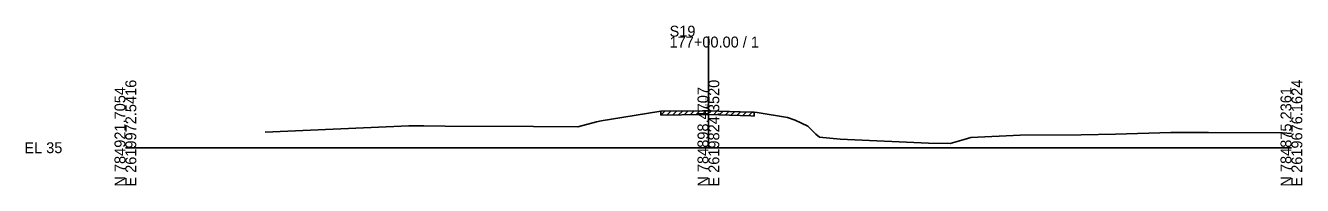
# Model space of a CAD drawing. Extents: x -26 to 1603, y -10 to 5028.
# Drawn here: x -25.7 to 302.8, y 1990.3 to 2031.4 of the extents above; entities that cross this region are included whole.
import ezdxf

# ---------------------------------------------------------------- set-up
doc = ezdxf.new("R2010")
doc.units = 0
for name, color, linetype in [('RD_GPK_XS_Cell', 7, 'Continuous'), ('RD_XS_ExGround', 7, 'Continuous'), ('RD_XS_ExPaveRet', 7, 'Continuous'), ('RD_XS_TX_Elev_EX', 7, 'Continuous')]:
    doc.layers.add(name, color=color, linetype=linetype)

msp = doc.modelspace()

# ---------------------------------------------------------------- linework, layer by layer
at = {"layer": 'RD_GPK_XS_Cell'}
for p, q in [((150, 2000), (150, 2028.57)), ((0, 2000), (150, 2000)), ((150, 2000), (300, 2000))]:
    msp.add_line(p, q, dxfattribs=at)
at = {"layer": 'RD_XS_ExGround'}
for p, q in [((122.45, 2006.93), (127.75, 2007.8)), ((127.75, 2007.8), (137.8, 2009.38)), ((137.8, 2009.38), (148.48, 2009.51)), ((148.48, 2009.51), (149.94, 2009.52)), ((149.94, 2009.52), (160.93, 2009.18)), ((160.93, 2009.18), (161.78, 2009.15)), ((161.78, 2009.15), (162.53, 2009.02)), ((162.53, 2009.02), (170.38, 2007.76)), ((170.38, 2007.76), (172.3, 2007.09)), ((35.98, 2003.99), (72.9, 2005.65)), ((72.9, 2005.65), (76.81, 2005.62)), ((76.81, 2005.62), (82.27, 2005.51)), ((82.27, 2005.51), (105.02, 2005.48)), ((105.02, 2005.48), (116.41, 2005.4)), ((116.41, 2005.4), (121.17, 2006.64)), ((121.17, 2006.64), (122.45, 2006.93)), ((172.3, 2007.09), (175.55, 2005.52)), ((175.55, 2005.52), (177.64, 2003.46)), ((177.64, 2003.46), (178.57, 2002.71)), ((178.57, 2002.71), (183.87, 2002.19)), ((183.87, 2002.19), (206.64, 2001.18)), ((206.64, 2001.18), (212.18, 2001.11)), ((212.18, 2001.11), (215.78, 2002.16)), ((215.78, 2002.16), (217.5, 2002.61)), ((217.5, 2002.61), (230.2, 2003.21)), ((230.2, 2003.21), (245.89, 2003.31)), ((245.89, 2003.31), (254.71, 2003.52)), ((254.71, 2003.52), (268.94, 2003.9)), ((268.94, 2003.9), (278.69, 2003.93)), ((278.69, 2003.93), (297.7, 2003.85)), ((297.7, 2003.85), (300, 2003.62))]:
    msp.add_line(p, q, dxfattribs=at)
at = {"layer": 'RD_XS_ExPaveRet'}
for p, q in [((137.8, 2008.38), (138.81, 2009.39)), ((137.8, 2008.38), (137.8, 2009.38)), ((137.8, 2008.38), (148.48, 2008.51)), ((139.3, 2008.39), (140.31, 2009.41)), ((140.8, 2008.41), (141.81, 2009.43)), ((142.3, 2008.43), (143.31, 2009.44)), ((143.8, 2008.45), (144.81, 2009.46)), ((145.3, 2008.47), (146.31, 2009.48)), ((146.8, 2008.49), (147.81, 2009.5)), ((148.3, 2008.5), (149.31, 2009.52)), ((148.48, 2008.51), (149.94, 2008.52)), ((149.8, 2008.52), (150.78, 2009.5)), ((149.94, 2008.52), (160.93, 2008.18)), ((151.3, 2008.48), (152.27, 2009.45)), ((152.8, 2008.43), (153.77, 2009.4)), ((154.3, 2008.39), (155.27, 2009.35)), ((155.8, 2008.34), (156.77, 2009.31)), ((157.3, 2008.29), (158.27, 2009.26)), ((158.8, 2008.24), (159.77, 2009.21)), ((160.3, 2008.2), (161.27, 2009.16)), ((160.93, 2008.18), (161.78, 2008.15)), ((161.78, 2009.15), (161.78, 2008.15))]:
    msp.add_line(p, q, dxfattribs=at)

# ---------------------------------------------------------------- texts
at = {"layer": 'RD_GPK_XS_Cell'}
for s, p in [('S19', (140, 2028.57)), ('177+00.00 / 1', (140, 2025.77)), ('EL 35', (-26, 1998.6))]:
    msp.add_text(s, height=2.8, dxfattribs=at).set_placement(p)
for s, p in [('E 2619972.5416', (2.8, 1990)), ('E 2619824.3520', (152.8, 1990)), ('E 2619676.1624', (302.8, 1990)), ('N 784921.7054', (0, 1990)), ('N 784898.4707', (150, 1990)), ('N 784875.2361', (300, 1990))]:
    msp.add_text(s, height=2.8, rotation=90, dxfattribs=at).set_placement(p)
at = {"layer": 'RD_XS_TX_Elev_EX'}
msp.add_text('44.52', height=0.8, rotation=90, dxfattribs=at).set_placement((149.9, 2009.96))

doc.saveas('drawing.dxf')
